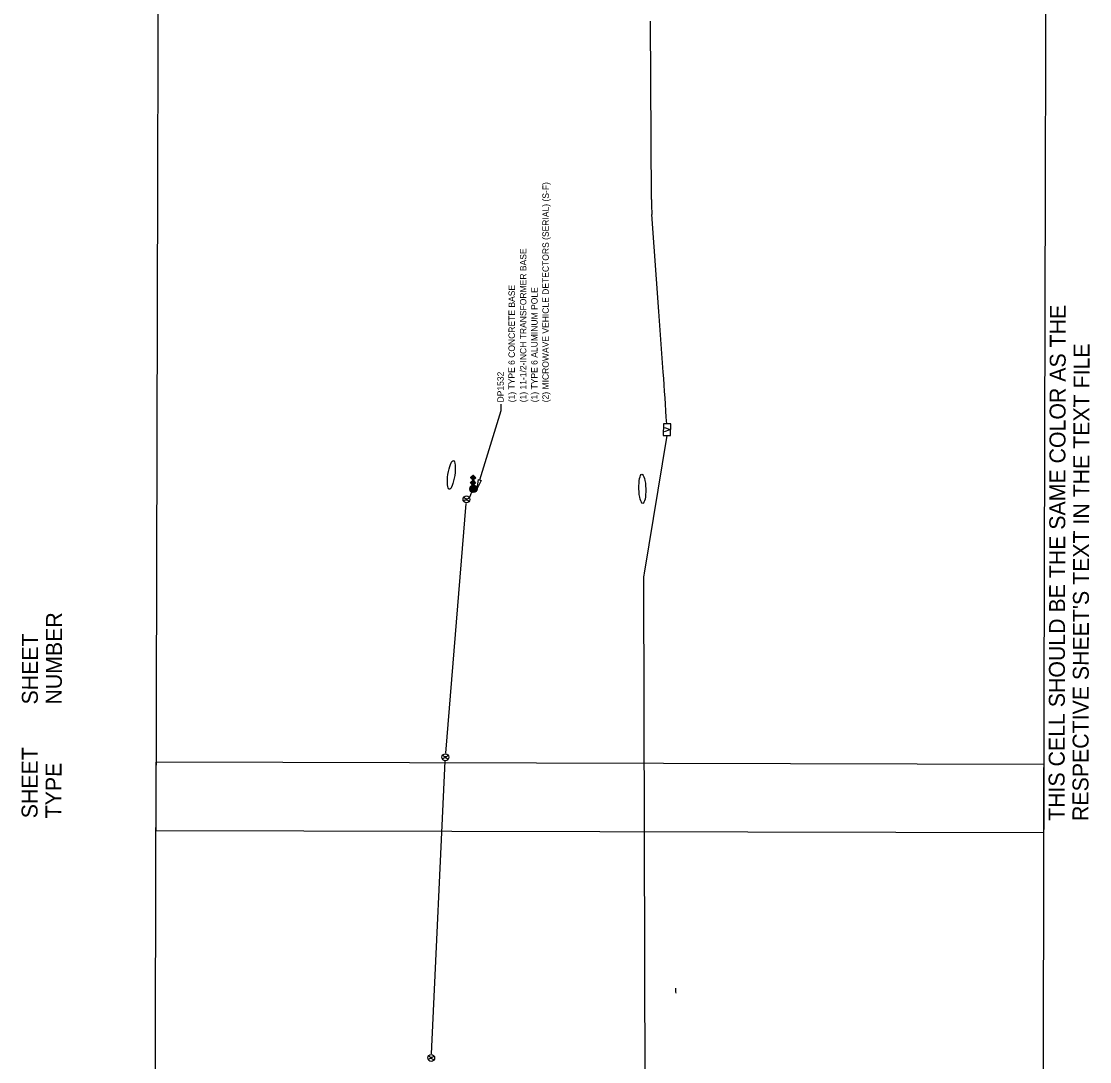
# Model space of a CAD drawing. Extents: x 601462 to 605493, y 331960 to 402715.
# Drawn here: x 602646 to 603819, y 376893 to 378036 of the extents above; entities that cross this region are included whole.
import ezdxf

# ---------------------------------------------------------------- set-up
doc = ezdxf.new("R2010")
doc.units = 0
for name, color, linetype in [('P_FTMS', 7, 'Continuous'), ('P_FTMSConduit', 7, 'Continuous'), ('P_MISC_TXT_1A (Construction)', 7, 'Continuous'), ('P_MISC_TXT_1B (Construction)', 7, 'Continuous')]:
    doc.layers.add(name, color=color, linetype=linetype)

# ---------------------------------------------------------------- blocks, each defined once
blk = doc.blocks.new('FTMS_FCV')
at = {"layer": 'P_FTMS'}
blk.add_line((12.7, 16.3), (0.6, -21.9), dxfattribs=at)
blk.add_lwpolyline([(39.1, 24.4), (-39.1, 24.4), (-39.1, -24.4), (39.1, -24.4)], close=True, dxfattribs=at)
blk.add_lwpolyline([(-12.1, 16.2), (0.6, -21.9)], dxfattribs=at)
blk = doc.blocks.new('_U231')
at = {"layer": 'P_FTMS'}
for p, q in [((12.1, 1.6), (-12.2, -0.1)), ((11.8, 3), (-12.1, 1.4)), ((11.9, 2.3), (-12.1, 0.6)), ((12.1, 0.8), (-12.1, -0.8)), ((12.1, 0.1), (-12.1, -1.6)), ((11.6, 3.7), (-12, 2.1)), ((-11.9, 2.5), (-11.4, -4.2)), ((11.3, 4.4), (-11.8, 2.9)), ((11, 5.2), (-11.6, 3.6)), ((10.6, 5.9), (-11.4, 4.4)), ((-11.3, 4.5), (-10.6, -6)), ((10.2, 6.6), (-11, 5.1)), ((9.8, 7.3), (-10.7, 5.9)), ((-10.7, 5.9), (-9.8, -7.2)), ((9.2, 8), (-10.2, 6.6)), ((-10, 6.9), (-9, -8.2)), ((8.6, 8.6), (-9.7, 7.4)), ((-9.3, 7.8), (-8.2, -9)), ((7.8, 9.3), (-9, 8.2)), ((-8.6, 8.5), (-7.4, -9.6)), ((6.9, 10), (-8.2, 9)), ((-8, 9.2), (-6.6, -10.2)), ((-7.3, 9.7), (-5.9, -10.6)), ((5.8, 10.7), (-7.2, 9.8)), ((-6.6, 10.3), (-5.1, -11)), ((4.5, 11.3), (-6, 10.6)), ((-5.9, 10.7), (-4.4, -11.4)), ((-5.1, 11), (-3.6, -11.6)), ((-4.4, 11.3), (-2.9, -11.8)), ((2.5, 11.9), (-4.1, 11.5)), ((-3.7, 11.6), (-2.1, -12)), ((-3, 11.8), (-1.4, -12.1)), ((-2.3, 12), (-0.6, -12.2)), ((-1.6, 12.1), (0.1, -12.2)), ((-0.8, 12.1), (0.8, -12.1)), ((-0.1, 12.2), (1.6, -12.1)), ((0.6, 12.1), (2.3, -11.9)), ((1.4, 12.1), (3, -11.8)), ((2.1, 12), (3.7, -11.6)), ((2.9, 11.8), (4.4, -11.3)), ((3.6, 11.6), (5.1, -11)), ((4.4, 11.3), (5.9, -10.7)), ((5.1, 11), (6.6, -10.2)), ((5.9, 10.6), (7.3, -9.8)), ((6.6, 10.2), (8, -9.2)), ((7.4, 9.7), (8.6, -8.6)), ((8.2, 9), (9.3, -7.8)), ((9, 8.2), (10, -6.9)), ((9.8, 7.2), (10.7, -5.8)), ((10.6, 5.9), (11.3, -4.5)), ((11.5, 4), (11.9, -2.5)), ((12.1, -0.6), (-12, -2.3)), ((12.1, -1.4), (-11.8, -3)), ((12, -2.1), (-11.6, -3.7)), ((11.8, -2.9), (-11.3, -4.4)), ((11.6, -3.6), (-11, -5.1)), ((11.3, -4.4), (-10.7, -5.9)), ((11.1, -5.1), (-10.2, -6.6)), ((10.6, -5.9), (-9.8, -7.3)), ((10.2, -6.6), (-9.2, -8)), ((9.6, -7.4), (-8.5, -8.6)), ((9, -8.2), (-7.8, -9.3)), ((8.2, -9), (-6.9, -10)), ((7.3, -9.8), (-5.8, -10.7)), ((6, -10.6), (-4.5, -11.3)), ((4.1, -11.5), (-2.6, -11.9))]:
    blk.add_line(p, q, dxfattribs=at)
blk.add_circle((0, 0), 12.2, dxfattribs=at)
blk = doc.blocks.new('FMD')
at = {"layer": 'P_FTMS'}
for p, q in [((16.9, 17.6), (-16.9, 17.6)), ((-16.1, 16.1), (-16.1, 18.4)), ((16.1, 16.1), (-16.1, 16.1)), ((15.5, 19), (-15.5, 19)), ((-14.6, 14.6), (-14.6, 19.9)), ((14.6, 14.6), (-14.6, 14.6)), ((14, 20.5), (-14, 20.5)), ((-13.2, 13.2), (-13.2, 21.3)), ((13.2, 13.2), (-13.2, 13.2)), ((12.5, 21.9), (-12.5, 21.9)), ((-11.7, 11.7), (-11.7, 22.8)), ((11.7, 11.7), (-11.7, 11.7)), ((11.1, 23.4), (-11.1, 23.4)), ((-10.2, 10.2), (-10.2, 24.2)), ((10.2, 10.2), (-10.2, 10.2)), ((9.6, 24.9), (-9.6, 24.9)), ((-8.8, 8.8), (-8.8, 25.7)), ((8.8, 8.8), (-8.8, 8.8)), ((8.2, 26.3), (-8.2, 26.3)), ((-7.3, 7.3), (-7.3, 27.2)), ((7.3, 7.3), (-7.3, 7.3)), ((6.7, 27.8), (-6.7, 27.8)), ((-5.9, 5.9), (-5.9, 28.6)), ((5.9, 5.9), (-5.9, 5.9)), ((5.2, 29.3), (-5.2, 29.3)), ((-4.4, 4.4), (-4.4, 30.1)), ((4.4, 4.4), (-4.4, 4.4)), ((3.8, 30.7), (-3.8, 30.7)), ((-2.9, 2.9), (-2.9, 31.6)), ((2.9, 2.9), (-2.9, 2.9)), ((2.3, 32.2), (-2.3, 32.2)), ((-1.5, 1.5), (-1.5, 33)), ((1.5, 1.5), (-1.5, 1.5)), ((0.8, 33.6), (-0.8, 33.6)), ((0, 0), (0, 34.5)), ((1.5, 1.5), (1.5, 33)), ((2.9, 2.9), (2.9, 31.6)), ((4.4, 4.4), (4.4, 30.1)), ((5.9, 5.9), (5.9, 28.6)), ((7.3, 7.3), (7.3, 27.2)), ((8.8, 8.8), (8.8, 25.7)), ((10.2, 10.2), (10.2, 24.2)), ((11.7, 11.7), (11.7, 22.8)), ((13.2, 13.2), (13.2, 21.3)), ((14.6, 14.6), (14.6, 19.9)), ((16.1, 16.1), (16.1, 18.4))]:
    blk.add_line(p, q, dxfattribs=at)
blk.add_lwpolyline([(-17.2, 17.2), (0, 34.5), (17.2, 17.2), (0, 0)], close=True, dxfattribs=at)

msp = doc.modelspace()

# ---------------------------------------------------------------- linework, layer by layer
at = {"layer": 'P_FTMS'}
for centre in [(603134.9, 377510.7), (603111.8, 377227.4), (603096.2, 376897.1)]:
    msp.add_circle(centre, 3.75, dxfattribs=at)
for centre, start, end in [((603134.6, 377506.3), 32.6299, 138.8855), ((603135.2, 377515.2), 212.6299, 318.8855), ((603111.5, 377223), 32.6299, 138.8855), ((603112.1, 377231.9), 212.6299, 318.8855), ((603095.8, 376892.7), 32.6299, 138.8855), ((603096.5, 376901.6), 212.6299, 318.8855)]:
    msp.add_arc(centre, 3.75, start, end, dxfattribs=at)
for centre, major_axis in [((603118.3, 377537.6), (-2.3, -15.8)), ((603328, 377522.3), (-0.4, 16))]:
    msp.add_ellipse(centre, major_axis=major_axis, ratio=0.23471, dxfattribs=at)
at = {"layer": 'P_FTMSConduit'}
for p, q in [((603337.9, 377840.2), (603336.9, 378035.9)), ((603346.2, 377717.2), (603338.5, 377823.6)), ((603351, 377650.5), (603346.2, 377717.2)), ((603355, 377581), (603330, 377429.7)), ((603140.5, 377518.8), (603138.1, 377512.8)), ((603112.1, 377231.9), (603134.6, 377506.3)), ((603329.3, 377421.4), (603332.9, 375897.8)), ((603096.5, 376901.6), (603111.5, 377223))]:
    msp.add_line(p, q, dxfattribs=at)
for points in [[(603149.6, 377532.1), (603173.1, 377608.2)], [(603173.1, 377608.2), (603173.1, 377615.2)]]:
    msp.add_lwpolyline(points, dxfattribs=at)
msp.add_lwpolyline([(603151.2, 377531.6), (603146.7, 377522.5), (603148, 377532.6)], close=True, dxfattribs=at)
for centre, radius, start, end in [((603587.9, 377841.5), 250, 180.2997, 184.1146), ((598329.1, 377289.3), 5034.9, 3.4682, 4.1146), ((603379.3, 377421.5), 50, 170.6261, 180.1357), ((603414.4, 376973.7), 50, 180.0822, 186.2074)]:
    msp.add_arc(centre, radius, start, end, dxfattribs=at)
at = {"layer": 'P_MISC_TXT_1A (Construction)'}
msp.add_lwpolyline([(603765, 375644.6), (603769, 377219.6), (602794, 377222.1), (602790, 375647.1)], close=True, dxfattribs=at)
msp.add_lwpolyline([(603765, 375644.6), (603769, 377219.6), (602794, 377222.1), (602790, 375647.1)], close=True, dxfattribs=at)
at = {"layer": 'P_MISC_TXT_1B (Construction)'}
msp.add_lwpolyline([(603768.8, 377144.6), (603772.9, 378719.6), (602797.9, 378722.1), (602793.8, 377147.1)], close=True, dxfattribs=at)
msp.add_lwpolyline([(603768.8, 377144.6), (603772.9, 378719.6), (602797.9, 378722.1), (602793.8, 377147.1)], close=True, dxfattribs=at)

# ---------------------------------------------------------------- block references
at = {"layer": 'P_FTMS'}
for name, p, xscale, yscale, rotation in [('FTMS_FCV', (603355.1, 377587.4), 0.16404166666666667, 0.16404166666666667, 88.76248754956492), ('FMD', (603139.4, 377534.7), 0.1640416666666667, 0.16404166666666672, -91.54665377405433), ('_U231', (603142.5, 377522.2), 0.32808333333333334, 0.32808333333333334, 2.5604819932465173), ('FMD', (603139.3, 377529.1), 0.1640416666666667, 0.16404166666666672, -91.54665377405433)]:
    msp.add_blockref(name, p, dxfattribs=dict(at, xscale=xscale, yscale=yscale, rotation=rotation))

# ---------------------------------------------------------------- texts
at = {"layer": 'P_FTMSConduit'}
for s, p in [('(2) MICROWAVE VEHICLE DETECTORS (SERIAL) (S-F)', (603225.2, 377617.4)), ('(1) 11-1/2-INCH TRANSFORMER BASE', (603200.6, 377617.4)), ('(1) TYPE 6 CONCRETE BASE', (603188, 377617.4)), ('(1) TYPE 6 ALUMINUM POLE', (603212.9, 377617.4)), ('DP1532', (603175.8, 377617.2))]:
    msp.add_text(s, height=7, rotation=89.9604, dxfattribs=at).set_placement(p)
at = {"layer": 'P_MISC_TXT_1B (Construction)'}
for s, p in [('THIS CELL SHOULD BE THE SAME COLOR AS THE', (603791.5, 377157.5)), ('THIS CELL SHOULD BE THE SAME COLOR AS THE', (603791.5, 377157.5)), ("RESPECTIVE SHEET'S TEXT IN THE TEXT FILE", (603817.7, 377157.4)), ("RESPECTIVE SHEET'S TEXT IN THE TEXT FILE", (603817.7, 377157.4)), ('NUMBER', (602690.6, 377285.3)), ('NUMBER', (602690.6, 377285.3)), ('SHEET', (602664.3, 377285.4)), ('SHEET', (602664.3, 377285.4)), ('SHEET', (602664, 377160.4)), ('SHEET', (602664, 377160.4)), ('TYPE', (602690.2, 377160.3)), ('TYPE', (602690.2, 377160.3))]:
    msp.add_text(s, height=17.5, rotation=89.8526, dxfattribs=at).set_placement(p)

doc.saveas('drawing.dxf')
